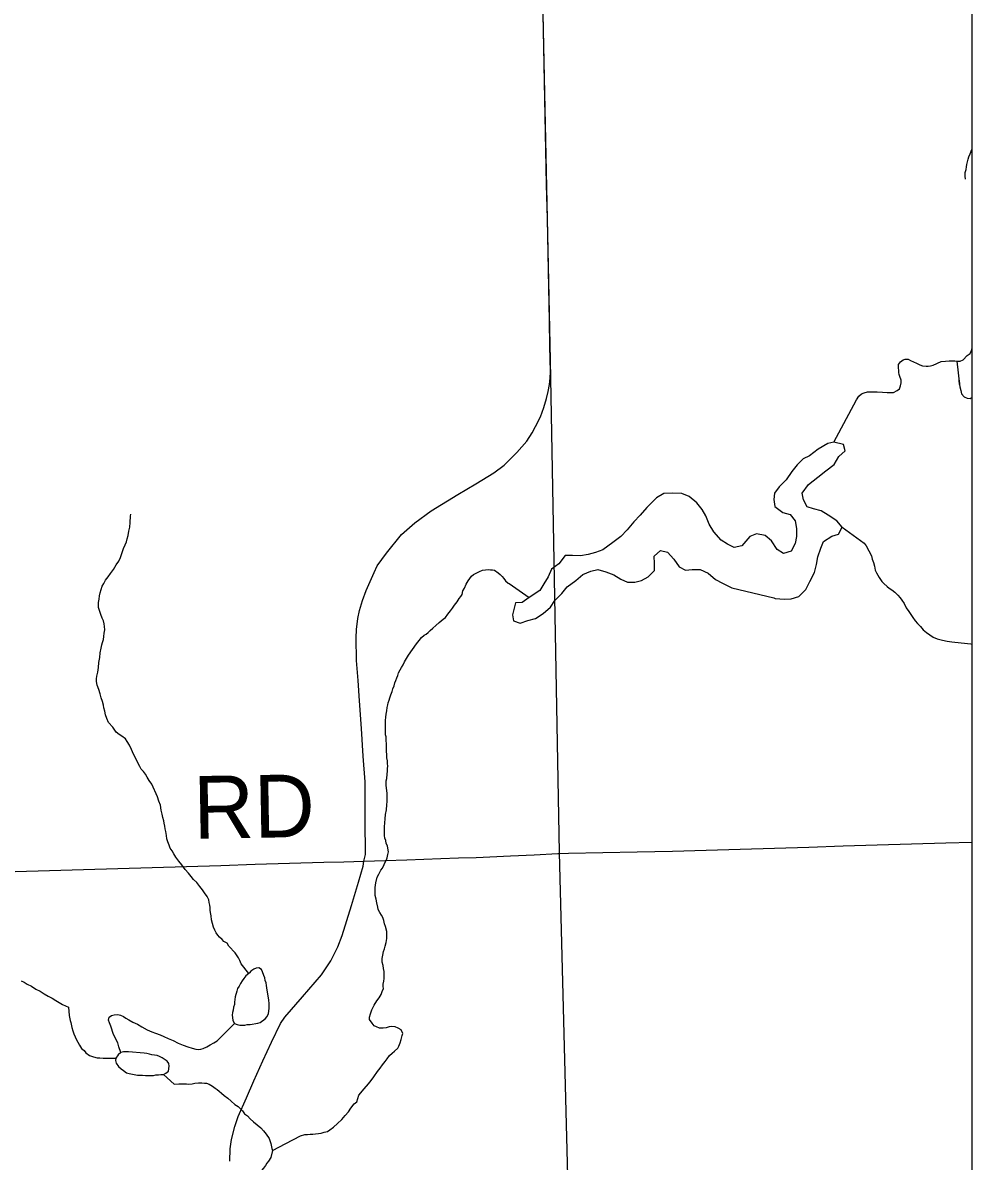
# Model space of a CAD drawing. Extents: x 103424 to 290657, y 38711 to 110967.
# Drawn here: x 171115 to 175680, y 86206 to 91682 of the extents above; entities that cross this region are included whole.
import ezdxf

# ---------------------------------------------------------------- set-up
doc = ezdxf.new("R2010")
doc.units = 0
for name, color, linetype in [('GM_X_Corporation', 7, 'Continuous'), ('GM_X_County_Road', 7, 'Continuous'), ('GM_X_Major_River', 7, 'Continuous'), ('GM_X_Minor_Lake', 7, 'Continuous'), ('GM_X_Minor_River', 7, 'Continuous'), ('GM_X_Township_Road', 7, 'Continuous'), ('GM_X_Township_Road_Text', 7, 'Continuous')]:
    doc.layers.add(name, color=color, linetype=linetype)

msp = doc.modelspace()

# ---------------------------------------------------------------- linework, layer by layer
at = {"layer": 'GM_X_Corporation'}
for points in [[(103423.7, 96534.8), (103423.7, 38711.2), (175679.7, 38711.2), (175679.7, 110967.2), (119699, 110967.2), (119716.9, 106542.5), (119719.8, 106322.8), (119720.8, 106006.3), (119709.7, 99445.7), (119706.4, 99064.2), (119663.9, 96690), (117026.4, 96688.2), (115542.1, 96665), (105081.7, 96574.5)], [(175679.7, 72246.4), (175679.7, 98096.3), (173478.4, 98058.2), (173550.7, 94746.5), (173649.8, 90059.6), (173693.6, 87690.3), (173775.2, 84514.7), (174054.1, 73155.3), (174066.9, 72315.5), (174070.5, 72208.9), (175615.6, 72242.7)]]:
    msp.add_lwpolyline(points, close=True, dxfattribs=at)
msp.add_lwpolyline([(148594.2, 97294.7), (158050.5, 97608.1), (158064.2, 97608.5), (162306.4, 97749.1), (162479.3, 97753.8), (165116.9, 97825.6), (173478.4, 98058.2), (173550.7, 94746.5), (173649.8, 90059.6), (173693.6, 87690.3), (173775.2, 84514.7), (174054.1, 73155.3), (174066.9, 72315.5), (174070.5, 72208.9), (173777.3, 72202), (169136.7, 72130.4), (166950.9, 72068.3), (161596.3, 71930.5), (161287.7, 71923.7), (157064.3, 71829.7), (151578, 71707.7), (149073.5, 71652)], dxfattribs=at)
at = {"layer": 'GM_X_County_Road'}
for points in [[(173640.7, 89908.6), (173646.7, 89942.3), (173650.2, 89973.8), (173651.5, 90003.7), (173649.7, 90126.4), (173647.9, 90250.8), (173643.9, 90408.9), (173640.4, 90573.9), (173637, 90739), (173633.5, 90904), (173630, 91069), (173626.6, 91234), (173623.1, 91399.1), (173619.6, 91564.1), (173616.2, 91729.1)], [(172110.5, 86205.2), (172112.8, 86265.5), (172118.4, 86309.3), (172134.5, 86371.9), (172151, 86420.9), (172189.9, 86511.2), (172225.5, 86591.8), (172268.6, 86688.8), (172310.6, 86778), (172354.1, 86868.3), (172375, 86897.9), (172460.1, 86996.8), (172550.7, 87101.7), (172596.8, 87168.8), (172630.1, 87236.6), (172651.1, 87292), (172695, 87435.5), (172729.4, 87547.5), (172751.9, 87624.7), (172755.3, 87649.4), (172762, 87681.6), (172761.3, 87846.7), (172760.9, 87938.4), (172760.5, 88030.1), (172751.6, 88154.4), (172743, 88287.6), (172734.3, 88420.8), (172726.9, 88518), (172719.6, 88615.2), (172717.5, 88722.8), (172720.2, 88763.7), (172726, 88816.6), (172733.1, 88855.1), (172747.8, 88903.3), (172766.3, 88951.6), (172804.6, 89038), (172819, 89069.2), (172863.4, 89131.5), (172936.3, 89220.6), (173000.1, 89277.4), (173078.3, 89334.1), (173207.4, 89412.9), (173293.9, 89464.9), (173380.3, 89517), (173430, 89554.7), (173490, 89614.4), (173537.6, 89669.3), (173564.4, 89709), (173580.8, 89740.3), (173603.9, 89785.9), (173620.8, 89832.1), (173633.1, 89875.5), (173640.7, 89908.6)]]:
    msp.add_lwpolyline(points, dxfattribs=at)
at = {"layer": 'GM_X_Major_River'}
for points in [[(175646.7, 90930.5), (175646.6, 90944.7), (175646.5, 90962.9), (175650.4, 90977.1), (175652.4, 90989.2), (175654.3, 91001.4), (175656.3, 91013.5), (175660.2, 91025.7), (175664.2, 91037.8), (175670.2, 91052), (175678.1, 91072.3), (175679.7, 91074.6)], [(175015.1, 89664.3), (175123.9, 89868.2), (175133.9, 89886.5), (175148, 89896.7), (175160.1, 89902.8), (175176.2, 89906.9), (175198.4, 89907), (175222.7, 89907.1), (175248.9, 89905.3), (175271.2, 89903.3), (175289.4, 89903.4), (175301.5, 89903.5), (175319.6, 89913.7), (175329.6, 89921.8), (175335.6, 89936), (175337.5, 89950.2), (175337.5, 89962.3), (175331.3, 89980.5), (175329.2, 89990.6), (175327.1, 90000.7), (175327.1, 90010.8), (175325, 90020.9), (175324.9, 90039.1), (175334.9, 90051.3), (175347, 90061.5), (175357, 90063.5), (175371.2, 90063.6), (175383.3, 90057.6), (175397.5, 90051.6), (175411.7, 90045.6), (175427.9, 90037.6), (175440.1, 90031.6), (175458.3, 90029.7), (175468.4, 90029.7), (175478.5, 90031.8), (175492.6, 90035.9), (175530.8, 90052.3), (175551, 90054.4), (175569.2, 90056.5), (175583.3, 90056.6), (175595.4, 90056.6), (175605.6, 90054.7), (175621.7, 90054.7), (175635.8, 90060.9), (175655.9, 90081.2), (175670, 90091.4), (175676, 90105.6), (175679.7, 90117.1)], [(175015.1, 89664.3), (174984.9, 89658.4), (174938.4, 89630.4), (174898, 89598.3), (174867.7, 89584.3), (174837.4, 89556.2), (174813, 89524.1), (174784.6, 89483.9), (174752.2, 89449.7), (174729.9, 89419.6), (174725.7, 89389.3), (174731.5, 89355), (174769.6, 89326.6), (174803.7, 89316.3), (174827.7, 89285.9), (174835.5, 89249.6), (174835.3, 89211.2), (174829.1, 89177), (174808.7, 89140.7), (174772.4, 89128.8), (174742.4, 89149.1), (174714.4, 89189.6), (174684.4, 89216), (174642.2, 89224.3), (174609.9, 89210.4), (174571.4, 89166.2), (174535.2, 89158.3), (174503.1, 89174.6), (174473, 89192.9), (174437, 89233.4), (174415.1, 89269.9), (174399.2, 89310.3)], [(175054.9, 89256.5), (175028.9, 89286.9), (174986.8, 89313.3), (174952.8, 89333.7), (174916.6, 89344), (174886.5, 89354.2), (174868.6, 89386.6), (174862.7, 89418.9), (174893.2, 89461.1), (174937.6, 89497.2), (174976.1, 89527.3), (175016.5, 89557.3), (175038.8, 89595.5), (175069.2, 89623.6), (175061.3, 89653.9), (175015.1, 89664.3)], [(174399.2, 89310.3), (174381.3, 89340.7), (174355.3, 89373.1), (174319.3, 89403.5), (174283.2, 89417.8), (174238.9, 89420.1), (174196.6, 89418.3), (174162.3, 89396.3), (174115.7, 89350.1), (174083.3, 89313.9), (174052.9, 89281.8), (174020.5, 89243.7), (173990.2, 89211.5), (173951.7, 89181.5), (173903.2, 89147.4), (173869, 89133.5), (173832.7, 89123.6), (173796.4, 89117.7), (173758.2, 89119.9), (173722, 89120.1), (173691.5, 89079.9), (173657.2, 89053.8), (173640.9, 89017.6), (173620.5, 88983.4), (173600.2, 88951.3), (173549.7, 88917.2)], [(174725.5, 88916), (174732.9, 88913.1), (174777.2, 88908.9), (174809.4, 88910.7), (174845.7, 88922.7), (174880.1, 88956.8), (174898.4, 88995), (174920.8, 89037.3), (174931.1, 89075.6), (174937.4, 89113.8), (174951.7, 89154.1), (174964, 89186.3), (175004.4, 89212.4), (175036.6, 89222.3), (175054.9, 89256.5)], [(173483.1, 88891.3), (173468.7, 88834.9), (173474.6, 88804.6), (173506.7, 88794.4), (173543, 88806.3), (173579.3, 88816.2), (173617.7, 88840.2), (173652, 88870.3), (173672.4, 88902.5), (173706.8, 88936.6), (173733.1, 88968.7), (173773.6, 88998.8), (173807.9, 89028.9), (173846.3, 89044.8), (173880.5, 89052.7), (173918.7, 89040.4), (173956.8, 89026.1), (173990.9, 89005.7), (174023, 88991.4), (174057.2, 88991.3), (174089.5, 88999.2), (174121.8, 89017.2), (174152.2, 89047.3), (174152.4, 89081.6), (174150.6, 89115.9), (174180.9, 89144), (174215.1, 89135.7), (174245, 89101.3), (174271, 89064.8), (174301.1, 89048.5), (174333.3, 89052.4), (174371.5, 89052.2), (174409.7, 89033.9), (174445.7, 89003.4), (174479.8, 88987.1), (174523.9, 88964.7), (174725.5, 88916)], [(172852.9, 87632.4), (172856.9, 87644.6), (172862.9, 87654.7), (172866.9, 87664.9), (172870.8, 87681.1), (172872.7, 87693.2), (172870.6, 87711.4), (172868.5, 87723.5), (172862.4, 87733.6), (172860.3, 87747.7), (172856.2, 87759.9), (172854.1, 87772), (172854, 87786.1), (172853.9, 87798.3), (172853.8, 87814.5), (172855.7, 87832.7), (172857.6, 87852.9), (172859.5, 87873.1), (172863.4, 87895.4), (172865.3, 87919.7), (172867.2, 87935.9), (172867.1, 87950), (172867.1, 87962.1), (172867, 87976.3), (172862.7, 88012.7), (172862.6, 88022.8), (172862.6, 88034.9), (172864.5, 88047.1), (172866.4, 88067.3), (172868.4, 88081.5), (172868.3, 88093.6), (172870.2, 88107.8), (172868.1, 88117.9), (172868, 88132), (172865.9, 88146.2), (172865.8, 88162.3), (172863.7, 88176.5), (172863.7, 88186.6), (172863.6, 88204.8), (172863.5, 88216.9), (172861.4, 88227.1), (172861.3, 88237.2), (172861.3, 88247.3), (172859.2, 88257.4), (172859.1, 88267.5), (172859.1, 88281.6), (172859, 88293.8), (172858.9, 88303.9), (172858.8, 88316), (172858.8, 88326.1), (172860.7, 88342.3), (172862.6, 88356.5), (172864.6, 88372.7), (172866.5, 88388.9), (172870.4, 88401), (172872.4, 88411.1), (172876.4, 88423.3), (172880.3, 88435.4), (172884.3, 88449.6), (172890.2, 88465.8), (172894.2, 88478), (172900.2, 88492.2), (172904.1, 88506.3), (172908.1, 88518.5), (172914.1, 88530.7), (172918.1, 88542.8), (172922, 88555), (172930, 88569.2), (172936, 88581.3), (172944, 88593.5), (172950, 88607.7), (172960, 88623.9), (172970, 88640.1), (173008, 88694.9), (173020.1, 88711.2), (173032.1, 88725.4), (173044.1, 88735.6), (173054.2, 88741.7), (173064.3, 88749.8), (173074.3, 88758), (173086.4, 88770.1), (173100.4, 88782.3), (173116.5, 88796.6), (173136.6, 88812.9), (173146.6, 88821), (173158.7, 88837.2), (173170.7, 88853.5), (173180.7, 88865.7), (173190.7, 88879.9), (173202.7, 88896.1), (173212.7, 88912.3), (173220.8, 88922.5), (173226.8, 88932.6), (173230.7, 88948.8), (173238.7, 88963), (173246.7, 88981.3), (173256.7, 88997.5), (173264.7, 89009.7), (173272.7, 89019.8), (173282.7, 89027.9), (173300.9, 89038.1)], [(173300.9, 89038.1), (173310.9, 89042.2), (173325, 89048.4), (173339.2, 89050.5), (173353.3, 89052.6), (173363.4, 89050.6), (173373.5, 89050.6), (173383.6, 89048.7), (173399.9, 89036.6), (173410, 89028.6), (173420.2, 89018.5), (173428.3, 89008.4), (173436.4, 88998.4), (173448.6, 88986.3), (173452.7, 88984.3), (173549.7, 88917.2)], [(173549.7, 88917.2), (173515.4, 88893.2), (173483.1, 88891.3)], [(172379.3, 86291.1), (172450.8, 86328.1), (172470.9, 86334.2), (172483.1, 86334.3), (172497.2, 86336.4), (172509.3, 86336.4), (172549.7, 86340.7), (172563.8, 86344.8), (172579.9, 86348.9), (172592, 86357.1), (172608.1, 86369.3), (172628.2, 86387.6), (172648.3, 86405.9), (172664.3, 86426.2), (172680.4, 86442.5), (172692.4, 86460.7), (172708.4, 86481), (172720.5, 86491.2), (172730.4, 86523.6), (172756.5, 86554.1), (172776.5, 86578.4), (172790.6, 86594.7), (172802.6, 86610.9), (172820.6, 86637.3), (172832.6, 86653.5), (172844.6, 86669.8), (172856.7, 86686), (172866.7, 86698.2), (172878.7, 86714.4), (172890.8, 86724.6), (172902.8, 86734.8), (172918.9, 86749), (172922.9, 86759.1), (172928.8, 86775.3), (172934.8, 86791.6), (172938.7, 86809.8), (172942.7, 86819.9), (172934.5, 86838.1), (172920.3, 86846.1), (172906.1, 86852.1), (172888, 86854), (172875.8, 86851.9), (172861.7, 86847.8), (172847.6, 86845.7), (172829.4, 86845.6), (172815.3, 86851.6), (172805.1, 86857.6), (172794.9, 86869.7), (172782.7, 86887.9), (172782.6, 86898), (172786.6, 86914.2), (172792.5, 86934.4), (172804.5, 86956.7), (172816.5, 86977), (172828.5, 86991.2), (172838.5, 87007.5), (172842.5, 87021.6), (172848.5, 87035.8), (172848.4, 87045.9), (172848.3, 87058.1), (172850.3, 87072.2), (172852.2, 87084.4), (172852.1, 87094.5), (172852.1, 87106.6), (172852, 87118.8), (172849.9, 87132.9), (172847.8, 87147.1), (172843.6, 87163.2), (172843.5, 87181.4), (172845.5, 87197.6), (172849.4, 87213.8), (172853.4, 87228), (172857.3, 87240.1), (172861.3, 87258.3), (172865.2, 87276.6), (172865.1, 87288.7), (172865, 87300.8), (172865, 87310.9), (172858.8, 87335.2), (172854.6, 87347.3), (172850.5, 87363.5), (172846.4, 87377.6), (172840.2, 87389.7), (172832.1, 87401.8), (172823.9, 87415.9), (172821.8, 87428), (172817.7, 87448.2), (172813.5, 87466.4), (172809.4, 87484.6), (172809.3, 87500.8), (172809.2, 87510.9), (172809.1, 87523), (172813, 87545.3), (172818.9, 87571.6), (172826.9, 87585.8), (172836.9, 87606.1), (172844.9, 87616.2), (172852.9, 87632.4)], [(172315.9, 86256.6), (172379.3, 86291.1)], [(172315.9, 86256.6), (172308, 86224.2), (172296, 86206), (172288, 86195.8), (172282, 86185.7), (172272, 86171.5), (172261.9, 86161.3), (172249.9, 86147.1), (172237.8, 86136.9), (172221.8, 86116.6), (172201.8, 86086.2)]]:
    msp.add_lwpolyline(points, dxfattribs=at)
at = {"layer": 'GM_X_Minor_Lake'}
for points in [[(172205.5, 87111.9), (172201.8, 87109.2), (172187.8, 87097), (172177.8, 87084.8), (172169.9, 87072.6), (172162, 87060.4), (172156, 87048.3), (172148.1, 87036.1), (172144.2, 87024), (172136.4, 86995.7), (172132.6, 86971.4), (172132.7, 86959.3), (172128.8, 86947.2), (172126.9, 86933), (172123, 86920.9), (172121.1, 86908.8), (172123.2, 86896.7), (172125.4, 86882.6), (172133.6, 86868.5), (172145.7, 86862.6), (172157.8, 86860.7), (172182, 86860.9), (172194.1, 86863), (172208.2, 86863.2), (172244.4, 86869.6), (172256.4, 86873.7)], [(172288.8, 87039.1), (172286.9, 87051.5), (172284.8, 87063.6), (172280.7, 87075.6), (172278.5, 87087.7), (172274.4, 87099.8), (172268.2, 87115.9), (172262, 87127.9), (172249.9, 87135.9), (172237.8, 87133.7), (172225.8, 87129.6), (172211.8, 87119.4), (172205.5, 87111.9)], [(172256.4, 86873.7), (172280.4, 86890), (172290.4, 86902.2), (172296.3, 86916.4), (172300.1, 86940.7), (172299.9, 86964.9), (172297.7, 86981), (172288.8, 87039.1)], [(171698.2, 86725.2), (171623.1, 86732.4), (171599, 86732.2), (171586.9, 86728), (171572.9, 86717.8), (171563, 86701.6), (171561.1, 86689.5), (171563.2, 86677.4), (171575.5, 86661.3), (171587.7, 86649.3)], [(171587.7, 86649.3), (171599.8, 86641.4), (171614, 86631.4), (171626.1, 86627.5), (171642.3, 86623.6), (171666.5, 86619.8), (171690.7, 86620), (171704.8, 86618.1), (171743.1, 86618.5), (171755.1, 86620.6), (171767.2, 86620.7), (171779.3, 86622.8), (171791.4, 86623), (171803.4, 86629.1), (171815.4, 86639.3), (171819.2, 86663.6), (171817.1, 86675.6), (171808.9, 86687.7), (171784.6, 86703.6), (171772.4, 86709.5), (171760.3, 86713.4), (171736.1, 86717.3), (171724, 86721.2), (171711.8, 86723.1), (171698.2, 86725.2)]]:
    msp.add_lwpolyline(points, dxfattribs=at)
at = {"layer": 'GM_X_Minor_River'}
for points in [[(175605.6, 90054.7), (175618.4, 89941.5), (175616.2, 89963.7), (175618.4, 89941.5), (175620.5, 89931.4), (175624.6, 89913.2), (175628.7, 89897), (175641, 89882.9), (175655.1, 89876.9), (175669.3, 89875), (175679.7, 89881.6)], [(171498.7, 88416.5), (171492.6, 88434.6), (171486.4, 88454.8), (171480.2, 88475), (171472, 88495.2), (171469.8, 88513.4), (171469.8, 88525.5), (171471.7, 88539.7), (171475.6, 88557.9), (171479.5, 88580.2), (171481.4, 88604.5), (171485.3, 88628.8), (171487.2, 88651), (171491.1, 88673.3), (171495, 88689.5), (171499, 88701.6), (171503, 88715.8), (171504.9, 88730), (171506.8, 88746.1), (171508.7, 88762.3), (171508.6, 88778.5), (171506.5, 88790.6), (171502.4, 88804.8), (171496.3, 88818.9), (171490.1, 88835.1), (171479.8, 88869.4), (171479.7, 88893.6), (171481.6, 88909.8), (171483.5, 88926), (171487.5, 88940.2), (171491.4, 88956.4), (171497.4, 88972.6), (171505.4, 88984.8), (171513.3, 89001), (171525.4, 89017.2), (171537.4, 89033.5), (171551.4, 89051.7), (171563.4, 89074.1), (171577.4, 89092.3), (171585.4, 89110.6), (171591.3, 89128.8), (171599.3, 89153.1), (171607.3, 89171.3), (171613.2, 89185.5), (171617.2, 89199.7), (171621.1, 89215.9), (171625, 89236.1), (171628.9, 89256.4), (171630.8, 89278.6), (171632.7, 89309), (171633.8, 89319)], [(175054.9, 89256.5), (175160.5, 89178.8), (175170.6, 89166.7), (175195.2, 89118.3), (175199.3, 89102.1), (175205.5, 89086), (175209.6, 89067.8), (175213.8, 89049.6), (175219.9, 89035.5), (175226, 89025.4), (175232.2, 89013.3), (175244.4, 88995.2), (175254.6, 88985.1), (175270.8, 88971), (175280.9, 88963), (175293.1, 88955), (175307.3, 88942.9), (175321.6, 88928.8), (175333.8, 88916.7), (175341.9, 88904.7), (175352.1, 88888.5), (175362.3, 88868.4), (175374.6, 88850.2), (175384.8, 88836.1), (175394.9, 88822), (175405.1, 88805.9), (175417.3, 88791.8), (175431.6, 88777.7), (175443.8, 88761.6), (175460, 88749.5), (175476.3, 88737.5), (175492.5, 88727.4), (175510.7, 88719.4), (175537, 88711.5), (175559.3, 88707.5), (175581.5, 88703.6), (175626, 88699.8), (175672.5, 88693.9), (175679.7, 88692.8)], [(172201.8, 87109.2), (172165, 87155.8), (172158.8, 87172), (172152.7, 87184.1), (172146.5, 87194.1), (172136.4, 87208.3), (172105.9, 87240.5), (172097.7, 87254.6), (172081.5, 87262.6), (172073.3, 87272.7), (172061.2, 87282.7), (172053, 87292.8), (172044.9, 87304.9), (172038.7, 87317), (172032.6, 87331.1), (172026.4, 87349.3), (172022.3, 87367.4), (172020.1, 87385.6), (172018, 87401.8), (172015.9, 87413.9), (172015.8, 87426.1), (172013.8, 87438.2), (172011.7, 87450.3), (172009.6, 87462.4), (172001.4, 87478.6), (171989.2, 87496.7), (171979, 87510.8), (171966.8, 87526.9), (171952.5, 87547.1), (171936.2, 87561.2), (171924, 87575.3), (171911.8, 87591.4), (171895.5, 87609.5), (171879.2, 87631.7), (171865, 87649.8), (171850.8, 87667.9), (171840.5, 87684.1), (171832.4, 87698.2), (171824.2, 87712.3), (171818.1, 87726.4), (171811.9, 87742.6), (171807.8, 87756.7), (171805.7, 87772.9), (171803.5, 87791), (171799.4, 87805.2), (171797.3, 87817.3), (171795.2, 87831.5), (171793.1, 87843.6), (171789, 87859.7), (171784.8, 87875.9), (171780.7, 87894.1), (171776.5, 87918.3), (171768.3, 87938.5), (171762.1, 87958.7), (171735.5, 88019.3), (171723.3, 88037.4), (171713.1, 88053.5), (171704.9, 88067.6), (171694.7, 88079.7), (171684.5, 88091.8), (171678.4, 88103.9), (171668.2, 88122), (171658, 88142.2), (171647.7, 88164.4), (171637.5, 88186.6), (171627.3, 88206.8), (171617.1, 88224.9), (171608.9, 88237), (171590.6, 88251.1), (171578.5, 88259.1), (171564.3, 88269.2), (171548, 88293.4), (171527.6, 88315.5), (171519.4, 88335.7), (171513.3, 88353.8), (171509.1, 88370), (171505, 88386.2), (171502.9, 88400.3), (171498.7, 88416.5)], [(171106.9, 87073.7), (171121.1, 87067.7), (171135.3, 87057.7), (171157.6, 87047.7), (171177.9, 87033.6), (171198.2, 87023.6), (171218.4, 87011.6), (171236.7, 86999.5), (171256.9, 86989.5), (171273.2, 86979.5), (171289.4, 86969.5), (171305.6, 86959.4), (171319.8, 86953.4), (171334, 86947.4), (171338.3, 86907), (171342.4, 86882.8), (171346.5, 86872.7), (171350.7, 86848.4), (171354.9, 86832.3), (171361, 86818.2), (171367.2, 86804), (171373.3, 86789.9), (171379.4, 86777.8), (171387.6, 86763.7), (171397.8, 86747.5), (171410, 86737.5), (171418.1, 86727.4), (171436.4, 86713.4), (171454.6, 86707.4), (171472.8, 86703.4), (171484.9, 86703.5), (171501.1, 86701.6), (171517.3, 86701.6), (171563, 86701.6)], [(171586.9, 86728), (171577.5, 86756.5), (171571.4, 86774.7), (171565.2, 86786.8), (171559.1, 86800.9), (171550.9, 86815), (171538.6, 86855.4), (171532.4, 86871.6), (171526.3, 86883.7), (171530.2, 86897.9), (171542.3, 86906), (171554.4, 86910.1), (171572.5, 86912.2), (171584.7, 86908.2), (171598.9, 86902.2), (171611, 86894.2), (171625.2, 86886.2), (171643.5, 86874.2), (171665.8, 86864.2), (171688.1, 86852.1), (171712.4, 86838.1), (171734.7, 86828.1), (171752.9, 86822.1), (171775.2, 86814.1), (171793.4, 86806.1), (171813.6, 86796.1), (171837.9, 86786.1), (171862.3, 86774.1), (171886.6, 86764.1), (171908.8, 86756.1), (171929.1, 86750.2), (171947.3, 86744.2), (171961.4, 86742.3), (171971.5, 86744.3), (171981.6, 86748.4), (171999.7, 86756.6)], [(171999.7, 86756.6), (172015.8, 86764.8), (172034, 86775), (172050.1, 86785.2), (172133.6, 86868.5)], [(171791.4, 86623), (171843.3, 86575.8), (171865.5, 86578), (171887.7, 86578.1), (171901.8, 86578.1), (171912, 86576.2), (171930.1, 86578.3), (171942.2, 86580.4), (171960.4, 86582.5), (171976.5, 86582.6), (171988.7, 86580.6), (171998.8, 86580.7), (172010.9, 86576.7), (172027.1, 86566.6), (172039.3, 86556.6), (172049.5, 86550.6), (172059.6, 86542.5), (172069.8, 86532.5), (172084, 86522.4), (172100.2, 86508.4), (172116.5, 86494.3), (172134.8, 86478.2), (172151, 86468.2), (172161.1, 86458.1), (172171.3, 86448), (172181.5, 86433.9), (172195.7, 86423.9), (172207.9, 86409.8), (172224.1, 86395.7), (172258.7, 86365.5), (172272.9, 86351.5), (172285.1, 86335.3), (172299.4, 86315.2), (172303.5, 86305.1), (172307.6, 86291), (172311.8, 86266.7), (172315.9, 86256.6)]]:
    msp.add_lwpolyline(points, dxfattribs=at)
at = {"layer": 'GM_X_Township_Road'}
msp.add_line((173687.5, 87685.2), (173693.1, 87685.4), dxfattribs=at)
for points in [[(173693.1, 87685.4), (173738, 87686.8), (173903, 87690.4), (174068.1, 87694.1), (174153.5, 87696), (174239, 87697.9), (174401.3, 87702.5), (174563.5, 87707.1), (174728.5, 87712.1), (174893.5, 87717.1), (175058.5, 87722.1), (175223.5, 87727), (175388.5, 87732), (175553.5, 87737), (175679.7, 87740.8)], [(171077.7, 87599.5), (171242.7, 87604.5), (171407.7, 87609.4), (171572.7, 87614.3), (171737.7, 87619.2), (171902.7, 87624.1), (172067.7, 87629), (172232.7, 87633.9), (172397.7, 87638.8), (172562.7, 87643.7), (172659, 87646.6), (172755.3, 87649.4)], [(172755.3, 87649.4), (172858, 87652.8), (172960.7, 87656.2), (173125.7, 87661.6), (173210, 87664.4), (173294.2, 87667.1), (173459.1, 87674.7), (173573.3, 87679.9), (173687.5, 87685.2)]]:
    msp.add_lwpolyline(points, dxfattribs=at)

# ---------------------------------------------------------------- texts
at = {"layer": 'GM_X_Township_Road_Text'}
msp.add_text('RD', height=301.87, rotation=0.9872, dxfattribs=at).set_placement((171937.6, 87756.2))

doc.saveas('drawing.dxf')
